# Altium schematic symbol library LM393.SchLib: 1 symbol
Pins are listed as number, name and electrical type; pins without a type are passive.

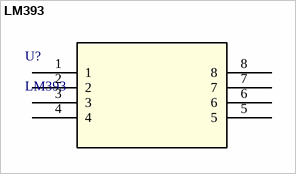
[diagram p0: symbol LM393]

## LM393
designator U?
Description; Manufacturer_Name: Texas Instruments
footprint DIP8_300
pins: 1, 2, 3, 4, 5, 6, 7, 8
